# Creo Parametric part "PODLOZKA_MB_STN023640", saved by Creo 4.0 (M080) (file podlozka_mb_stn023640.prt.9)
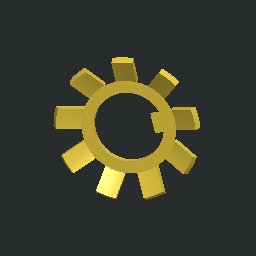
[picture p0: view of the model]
Units: millimeter Newton Second (mmNs); MM, TONNE, SECS
Materials in the file: OCEL_N

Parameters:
  NAZOV = "PODLOZKA_MB_STN023640"
  NORMA = "STN 02 3640"
  PTC_MATERIAL_NAME = "OCEL_N"

Other parameters: HMOTNOST, HUSTOTA, D9, D10

Created from: PODLOZKA_MB_STN_023640.PRT

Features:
  1. datum plane "DTM1"
  2. protrusion
  3. pattern
  4. datum plane "DTM2"
  5. cut
  6. cut
  7. cut
  8. cut
  9. cut
  10. cut
  11. cut
  12. cut
  13. cut

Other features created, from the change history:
  extruded cut "Cut id 981"
  extruded cut "Cut id 982"
  extruded cut "Cut id 1095"
  extruded cut "Cut id 1096"

Layers: 05_OSI, ALL_AXIS, ALL_DATUM_PLANES, ALL_THREAD

Family table entries: GENERIC, PODLOZKA_MB0, PODLOZKA_MB_STN023640, value(d_val), value(i_val), 2/!, 2/+, 2/5, 2/$, PODLOZKA_MB1, PODLOZKA_MB_STN023640, 2/%, 2/1, 2/9, 2/(, PODLOZKA_MB2, PODLOZKA_MB_STN023640, 2/+, 2/5, 2/<, 2/., PODLOZKA_MB3, PODLOZKA_MB_STN023640, 2//, 2/8, 2/@, 2/1, PODLOZKA_MB4, PODLOZKA_MB_STN023640, 2/9, 2/B, 2/4, PODLOZKA_MB5, PODLOZKA_MB_STN023640, 2/7, 2/@, 2/E, 2/9, PODLOZKA_MB6, PODLOZKA_MB_STN023640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

Surfaces: 23 plane, 3 cone, 1 cylinder, 1 torus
